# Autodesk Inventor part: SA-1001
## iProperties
Created: 2006-03
Part Number: SA-1001
Material: Aluminum-6061
Document SubType Name: Modeling
Designer: Administrator
Stock Number: P-1267
Density: 2.71 g/cm^3
Author: Administrator
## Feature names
1. Extrusion1
2. Hole1
3. Hole2
4. Split1
5. Fillet1
